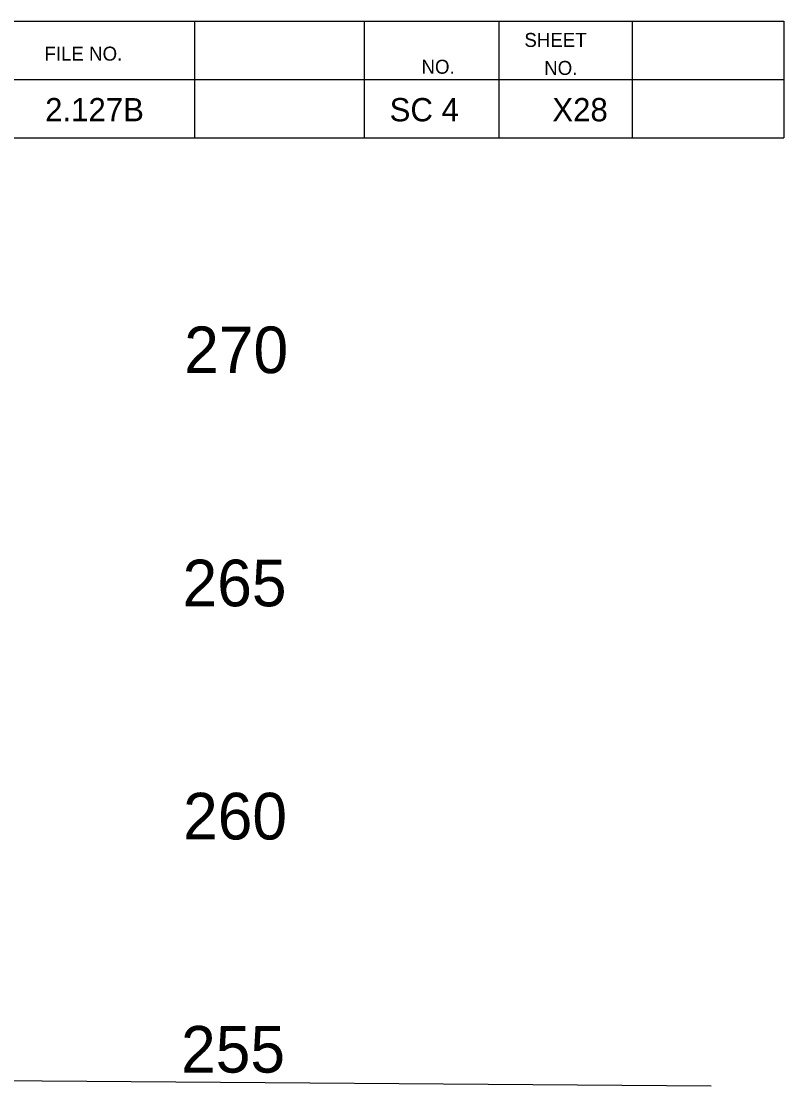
# Model space of a CAD drawing. Extents: x 1000 to 1162, y 999 to 8520.
# Drawn here: x 1145.2 to 1161.56, y 4184.72 to 4207.55 of the extents above; entities that cross this region are included whole.
import ezdxf

# ---------------------------------------------------------------- set-up
doc = ezdxf.new("R2010")
doc.units = 0
for name, color, linetype in [('Level 11', 7, 'Continuous'), ('Level 20', 7, 'Continuous'), ('Level 3', 7, 'Continuous'), ('Level 60', 7, 'Continuous')]:
    doc.layers.add(name, color=color, linetype=linetype)

msp = doc.modelspace()

# ---------------------------------------------------------------- linework, layer by layer
at = {"layer": 'Level 3'}
for p, q in [((1133.055, 4207.546), (1161.555, 4207.546)), ((1133.055, 4207.546), (1161.555, 4207.546)), ((1133.055, 4207.546), (1161.555, 4207.546)), ((1133.055, 4207.546), (1161.555, 4207.546)), ((1133.055, 4207.546), (1161.555, 4207.546)), ((1133.055, 4207.546), (1161.555, 4207.546)), ((1133.055, 4207.546), (1161.555, 4207.546)), ((1133.055, 4207.546), (1161.555, 4207.546)), ((1133.055, 4207.546), (1161.555, 4207.546)), ((1133.055, 4207.546), (1161.555, 4207.546)), ((1133.055, 4207.546), (1161.555, 4207.546)), ((1133.055, 4207.546), (1161.555, 4207.546)), ((1133.055, 4207.546), (1161.555, 4207.546)), ((1133.055, 4207.546), (1161.555, 4207.546)), ((1133.055, 4207.546), (1161.555, 4207.546)), ((1133.055, 4207.546), (1161.555, 4207.546)), ((1133.055, 4207.546), (1161.555, 4207.546)), ((1133.055, 4207.546), (1161.555, 4207.546)), ((1133.055, 4207.546), (1161.555, 4207.546)), ((1133.055, 4207.546), (1161.555, 4207.546)), ((1133.055, 4207.546), (1161.555, 4207.546)), ((1133.055, 4207.546), (1161.555, 4207.546)), ((1133.055, 4207.546), (1161.555, 4207.546)), ((1133.055, 4207.546), (1161.555, 4207.546)), ((1133.055, 4207.546), (1161.555, 4207.546)), ((1133.055, 4207.546), (1161.555, 4207.546)), ((1148.913, 4207.546), (1148.913, 4205.046)), ((1148.913, 4207.546), (1148.913, 4205.046)), ((1148.913, 4207.546), (1148.913, 4205.046)), ((1148.913, 4207.546), (1148.913, 4205.046)), ((1148.913, 4207.546), (1148.913, 4205.046)), ((1148.913, 4207.546), (1148.913, 4205.046)), ((1148.913, 4207.546), (1148.913, 4205.046)), ((1148.913, 4207.546), (1148.913, 4205.046)), ((1148.913, 4207.546), (1148.913, 4205.046)), ((1148.913, 4207.546), (1148.913, 4205.046)), ((1148.913, 4207.546), (1148.913, 4205.046)), ((1148.913, 4207.546), (1148.913, 4205.046)), ((1148.913, 4207.546), (1148.913, 4205.046)), ((1148.913, 4207.546), (1148.913, 4205.046)), ((1148.913, 4207.546), (1148.913, 4205.046)), ((1148.913, 4207.546), (1148.913, 4205.046)), ((1148.913, 4207.546), (1148.913, 4205.046)), ((1148.913, 4207.546), (1148.913, 4205.046)), ((1148.913, 4207.546), (1148.913, 4205.046)), ((1148.913, 4207.546), (1148.913, 4205.046)), ((1148.913, 4207.546), (1148.913, 4205.046)), ((1148.913, 4207.546), (1148.913, 4205.046)), ((1148.913, 4207.546), (1148.913, 4205.046)), ((1148.913, 4207.546), (1148.913, 4205.046)), ((1148.913, 4207.546), (1148.913, 4205.046)), ((1148.913, 4207.546), (1148.913, 4205.046)), ((1152.554, 4207.546), (1152.554, 4205.046)), ((1152.554, 4207.546), (1152.554, 4205.046)), ((1152.554, 4207.546), (1152.554, 4205.046)), ((1152.554, 4207.546), (1152.554, 4205.046)), ((1152.554, 4207.546), (1152.554, 4205.046)), ((1152.554, 4207.546), (1152.554, 4205.046)), ((1152.554, 4207.546), (1152.554, 4205.046)), ((1152.554, 4207.546), (1152.554, 4205.046)), ((1152.554, 4207.546), (1152.554, 4205.046)), ((1152.554, 4207.546), (1152.554, 4205.046)), ((1152.554, 4207.546), (1152.554, 4205.046)), ((1152.554, 4207.546), (1152.554, 4205.046)), ((1152.554, 4207.546), (1152.554, 4205.046)), ((1152.554, 4207.546), (1152.554, 4205.046)), ((1152.554, 4207.546), (1152.554, 4205.046)), ((1152.554, 4207.546), (1152.554, 4205.046)), ((1152.554, 4207.546), (1152.554, 4205.046)), ((1152.554, 4207.546), (1152.554, 4205.046)), ((1152.554, 4207.546), (1152.554, 4205.046)), ((1152.554, 4207.546), (1152.554, 4205.046)), ((1152.554, 4207.546), (1152.554, 4205.046)), ((1152.554, 4207.546), (1152.554, 4205.046)), ((1152.554, 4207.546), (1152.554, 4205.046)), ((1152.554, 4207.546), (1152.554, 4205.046)), ((1152.554, 4207.546), (1152.554, 4205.046)), ((1152.554, 4207.546), (1152.554, 4205.046)), ((1155.44, 4207.546), (1155.44, 4205.046)), ((1155.44, 4207.546), (1155.44, 4205.046)), ((1155.44, 4207.546), (1155.44, 4205.046)), ((1155.44, 4207.546), (1155.44, 4205.046)), ((1155.44, 4207.546), (1155.44, 4205.046)), ((1155.44, 4207.546), (1155.44, 4205.046)), ((1155.44, 4207.546), (1155.44, 4205.046)), ((1155.44, 4207.546), (1155.44, 4205.046)), ((1155.44, 4207.546), (1155.44, 4205.046)), ((1155.44, 4207.546), (1155.44, 4205.046)), ((1155.44, 4207.546), (1155.44, 4205.046)), ((1155.44, 4207.546), (1155.44, 4205.046)), ((1155.44, 4207.546), (1155.44, 4205.046)), ((1155.44, 4207.546), (1155.44, 4205.046)), ((1155.44, 4207.546), (1155.44, 4205.046)), ((1155.44, 4207.546), (1155.44, 4205.046)), ((1155.44, 4207.546), (1155.44, 4205.046)), ((1155.44, 4207.546), (1155.44, 4205.046)), ((1155.44, 4207.546), (1155.44, 4205.046)), ((1155.44, 4207.546), (1155.44, 4205.046)), ((1155.44, 4207.546), (1155.44, 4205.046)), ((1155.44, 4207.546), (1155.44, 4205.046)), ((1155.44, 4207.546), (1155.44, 4205.046)), ((1155.44, 4207.546), (1155.44, 4205.046)), ((1155.44, 4207.546), (1155.44, 4205.046)), ((1155.44, 4207.546), (1155.44, 4205.046)), ((1158.305, 4207.546), (1158.305, 4205.046)), ((1158.305, 4207.546), (1158.305, 4205.046)), ((1158.305, 4207.546), (1158.305, 4205.046)), ((1158.305, 4207.546), (1158.305, 4205.046)), ((1158.305, 4207.546), (1158.305, 4205.046)), ((1158.305, 4207.546), (1158.305, 4205.046)), ((1158.305, 4207.546), (1158.305, 4205.046)), ((1158.305, 4207.546), (1158.305, 4205.046)), ((1158.305, 4207.546), (1158.305, 4205.046)), ((1158.305, 4207.546), (1158.305, 4205.046)), ((1158.305, 4207.546), (1158.305, 4205.046)), ((1158.305, 4207.546), (1158.305, 4205.046)), ((1158.305, 4207.546), (1158.305, 4205.046)), ((1158.305, 4207.546), (1158.305, 4205.046)), ((1158.305, 4207.546), (1158.305, 4205.046)), ((1158.305, 4207.546), (1158.305, 4205.046)), ((1158.305, 4207.546), (1158.305, 4205.046)), ((1158.305, 4207.546), (1158.305, 4205.046)), ((1158.305, 4207.546), (1158.305, 4205.046)), ((1158.305, 4207.546), (1158.305, 4205.046)), ((1158.305, 4207.546), (1158.305, 4205.046)), ((1158.305, 4207.546), (1158.305, 4205.046)), ((1158.305, 4207.546), (1158.305, 4205.046)), ((1158.305, 4207.546), (1158.305, 4205.046)), ((1158.305, 4207.546), (1158.305, 4205.046)), ((1158.305, 4207.546), (1158.305, 4205.046)), ((1161.555, 4207.546), (1161.555, 4205.046)), ((1161.555, 4207.546), (1161.555, 4205.046)), ((1161.555, 4207.546), (1161.555, 4205.046)), ((1161.555, 4207.546), (1161.555, 4205.046)), ((1161.555, 4207.546), (1161.555, 4205.046)), ((1161.555, 4207.546), (1161.555, 4205.046)), ((1161.555, 4207.546), (1161.555, 4205.046)), ((1161.555, 4207.546), (1161.555, 4205.046)), ((1161.555, 4207.546), (1161.555, 4205.046)), ((1161.555, 4207.546), (1161.555, 4205.046)), ((1161.555, 4207.546), (1161.555, 4205.046)), ((1161.555, 4207.546), (1161.555, 4205.046)), ((1161.555, 4207.546), (1161.555, 4205.046)), ((1161.555, 4207.546), (1161.555, 4205.046)), ((1161.555, 4207.546), (1161.555, 4205.046)), ((1161.555, 4207.546), (1161.555, 4205.046)), ((1161.555, 4207.546), (1161.555, 4205.046)), ((1161.555, 4207.546), (1161.555, 4205.046)), ((1161.555, 4207.546), (1161.555, 4205.046)), ((1161.555, 4207.546), (1161.555, 4205.046)), ((1161.555, 4207.546), (1161.555, 4205.046)), ((1161.555, 4207.546), (1161.555, 4205.046)), ((1161.555, 4207.546), (1161.555, 4205.046)), ((1161.555, 4207.546), (1161.555, 4205.046)), ((1161.555, 4207.546), (1161.555, 4205.046)), ((1161.555, 4207.546), (1161.555, 4205.046)), ((1133.055, 4206.296), (1161.555, 4206.296)), ((1133.055, 4206.296), (1161.555, 4206.296)), ((1133.055, 4206.296), (1161.555, 4206.296)), ((1133.055, 4206.296), (1161.555, 4206.296)), ((1133.055, 4206.296), (1161.555, 4206.296)), ((1133.055, 4206.296), (1161.555, 4206.296)), ((1133.055, 4206.296), (1161.555, 4206.296)), ((1133.055, 4206.296), (1161.555, 4206.296)), ((1133.055, 4206.296), (1161.555, 4206.296)), ((1133.055, 4206.296), (1161.555, 4206.296)), ((1133.055, 4206.296), (1161.555, 4206.296)), ((1133.055, 4206.296), (1161.555, 4206.296)), ((1133.055, 4206.296), (1161.555, 4206.296)), ((1133.055, 4206.296), (1161.555, 4206.296)), ((1133.055, 4206.296), (1161.555, 4206.296)), ((1133.055, 4206.296), (1161.555, 4206.296)), ((1133.055, 4206.296), (1161.555, 4206.296)), ((1133.055, 4206.296), (1161.555, 4206.296)), ((1133.055, 4206.296), (1161.555, 4206.296)), ((1133.055, 4206.296), (1161.555, 4206.296)), ((1133.055, 4206.296), (1161.555, 4206.296)), ((1133.055, 4206.296), (1161.555, 4206.296)), ((1133.055, 4206.296), (1161.555, 4206.296)), ((1133.055, 4206.296), (1161.555, 4206.296)), ((1133.055, 4206.296), (1161.555, 4206.296)), ((1133.055, 4206.296), (1161.555, 4206.296)), ((1133.055, 4205.046), (1161.555, 4205.046)), ((1133.055, 4205.046), (1161.555, 4205.046)), ((1133.055, 4205.046), (1161.555, 4205.046)), ((1133.055, 4205.046), (1161.555, 4205.046)), ((1133.055, 4205.046), (1161.555, 4205.046)), ((1133.055, 4205.046), (1161.555, 4205.046)), ((1133.055, 4205.046), (1161.555, 4205.046)), ((1133.055, 4205.046), (1161.555, 4205.046)), ((1133.055, 4205.046), (1161.555, 4205.046)), ((1133.055, 4205.046), (1161.555, 4205.046)), ((1133.055, 4205.046), (1161.555, 4205.046)), ((1133.055, 4205.046), (1161.555, 4205.046)), ((1133.055, 4205.046), (1161.555, 4205.046)), ((1133.055, 4205.046), (1161.555, 4205.046)), ((1133.055, 4205.046), (1161.555, 4205.046)), ((1133.055, 4205.046), (1161.555, 4205.046)), ((1133.055, 4205.046), (1161.555, 4205.046)), ((1133.055, 4205.046), (1161.555, 4205.046)), ((1133.055, 4205.046), (1161.555, 4205.046)), ((1133.055, 4205.046), (1161.555, 4205.046)), ((1133.055, 4205.046), (1161.555, 4205.046)), ((1133.055, 4205.046), (1161.555, 4205.046)), ((1133.055, 4205.046), (1161.555, 4205.046)), ((1133.055, 4205.046), (1161.555, 4205.046)), ((1133.055, 4205.046), (1161.555, 4205.046))]:
    msp.add_line(p, q, dxfattribs=at)
at = {"layer": 'Level 60'}
msp.add_line((1111.704, 4185.071), (1160, 4184.719), dxfattribs=at)

# ---------------------------------------------------------------- texts
at = {"layer": 'Level 11'}
for s, p in [(' 270', (1148.319, 4200)), (' 265', (1148.284, 4195)), (' 260', (1148.295, 4190)), (' 255', (1148.252, 4185))]:
    msp.add_text(s, height=1, dxfattribs=at).set_placement(p)
at = {"layer": 'Level 20'}
for s, p in [('2.127B', (1145.707, 4205.4)), ('SC 4', (1153.099, 4205.4)), ('X28', (1156.59, 4205.4))]:
    msp.add_text(s, height=0.5, dxfattribs=at).set_placement(p)
at = {"layer": 'Level 3'}
for s, p in [('SHEET', (1155.99, 4206.996)), ('SHEET', (1155.99, 4206.996)), ('SHEET', (1155.99, 4206.996)), ('SHEET', (1155.99, 4206.996)), ('SHEET', (1155.99, 4206.996)), ('SHEET', (1155.99, 4206.996)), ('SHEET', (1155.99, 4206.996)), ('SHEET', (1155.99, 4206.996)), ('SHEET', (1155.99, 4206.996)), ('SHEET', (1155.99, 4206.996)), ('SHEET', (1155.99, 4206.996)), ('SHEET', (1155.99, 4206.996)), ('SHEET', (1155.99, 4206.996)), ('SHEET', (1155.99, 4206.996)), ('SHEET', (1155.99, 4206.996)), ('SHEET', (1155.99, 4206.996)), ('SHEET', (1155.99, 4206.996)), ('SHEET', (1155.99, 4206.996)), ('SHEET', (1155.99, 4206.996)), ('SHEET', (1155.99, 4206.996)), ('SHEET', (1155.99, 4206.996)), ('SHEET', (1155.99, 4206.996)), ('SHEET', (1155.99, 4206.996)), ('SHEET', (1155.99, 4206.996)), ('SHEET', (1155.99, 4206.996)), ('SHEET', (1155.99, 4206.996)), ('FILE NO.', (1145.691, 4206.702)), ('FILE NO.', (1145.691, 4206.702)), ('FILE NO.', (1145.691, 4206.702)), ('FILE NO.', (1145.691, 4206.702)), ('FILE NO.', (1145.691, 4206.702)), ('FILE NO.', (1145.691, 4206.702)), ('FILE NO.', (1145.691, 4206.702)), ('FILE NO.', (1145.691, 4206.702)), ('FILE NO.', (1145.691, 4206.702)), ('FILE NO.', (1145.691, 4206.702)), ('FILE NO.', (1145.691, 4206.702)), ('FILE NO.', (1145.691, 4206.702)), ('FILE NO.', (1145.691, 4206.702)), ('FILE NO.', (1145.691, 4206.702)), ('FILE NO.', (1145.691, 4206.702)), ('FILE NO.', (1145.691, 4206.702)), ('FILE NO.', (1145.691, 4206.702)), ('FILE NO.', (1145.691, 4206.702)), ('FILE NO.', (1145.691, 4206.702)), ('FILE NO.', (1145.691, 4206.702)), ('FILE NO.', (1145.691, 4206.702)), ('FILE NO.', (1145.691, 4206.702)), ('FILE NO.', (1145.691, 4206.702)), ('FILE NO.', (1145.691, 4206.702)), ('FILE NO.', (1145.691, 4206.702)), ('FILE NO.', (1145.691, 4206.702)), ('NO.', (1153.782, 4206.421)), ('NO.', (1153.782, 4206.421)), ('NO.', (1153.782, 4206.421)), ('NO.', (1153.782, 4206.421)), ('NO.', (1153.782, 4206.421)), ('NO.', (1153.782, 4206.421)), ('NO.', (1153.782, 4206.421)), ('NO.', (1153.782, 4206.421)), ('NO.', (1153.782, 4206.421)), ('NO.', (1153.782, 4206.421)), ('NO.', (1153.782, 4206.421)), ('NO.', (1153.782, 4206.421)), ('NO.', (1153.782, 4206.421)), ('NO.', (1153.782, 4206.421)), ('NO.', (1153.782, 4206.421)), ('NO.', (1153.782, 4206.421)), ('NO.', (1153.782, 4206.421)), ('NO.', (1153.782, 4206.421)), ('NO.', (1153.782, 4206.421)), ('NO.', (1153.782, 4206.421)), ('NO.', (1153.782, 4206.421)), ('NO.', (1153.782, 4206.421)), ('NO.', (1153.782, 4206.421)), ('NO.', (1153.782, 4206.421)), ('NO.', (1153.782, 4206.421)), ('NO.', (1153.782, 4206.421)), ('NO.', (1156.415, 4206.396)), ('NO.', (1156.415, 4206.396)), ('NO.', (1156.415, 4206.396)), ('NO.', (1156.415, 4206.396)), ('NO.', (1156.415, 4206.396)), ('NO.', (1156.415, 4206.396)), ('NO.', (1156.415, 4206.396)), ('NO.', (1156.415, 4206.396)), ('NO.', (1156.415, 4206.396)), ('NO.', (1156.415, 4206.396)), ('NO.', (1156.415, 4206.396)), ('NO.', (1156.415, 4206.396)), ('NO.', (1156.415, 4206.396)), ('NO.', (1156.415, 4206.396)), ('NO.', (1156.415, 4206.396)), ('NO.', (1156.415, 4206.396)), ('NO.', (1156.415, 4206.396)), ('NO.', (1156.415, 4206.396)), ('NO.', (1156.415, 4206.396)), ('NO.', (1156.415, 4206.396)), ('NO.', (1156.415, 4206.396)), ('NO.', (1156.415, 4206.396)), ('NO.', (1156.415, 4206.396)), ('NO.', (1156.415, 4206.396)), ('NO.', (1156.415, 4206.396)), ('NO.', (1156.415, 4206.396))]:
    msp.add_text(s, height=0.3, dxfattribs=at).set_placement(p)

doc.saveas('drawing.dxf')
